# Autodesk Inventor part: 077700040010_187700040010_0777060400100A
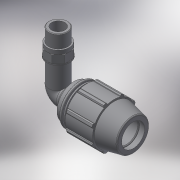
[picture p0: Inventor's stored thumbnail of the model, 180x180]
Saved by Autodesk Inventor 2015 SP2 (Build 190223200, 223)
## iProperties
Created: 2017-02
Part Number: 077700040010_187700040010_0777060400100A
Material: Generic
Description: PLASSON 90° ELBOW MALE WITH INTEGRAL BRASS THREAD 40-1"
Document SubType Name: Modeling
Designer: KIM
Mass: 174.249 g
Surface Area: 431.906 cm^2
Volume: 174.249 cm^3
Density: 1 g/cm^3
Appearance: Default
Author: KIM
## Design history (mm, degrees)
derived "07770.ipt"
feature "Solid1::07770.ipt"
tag "TaggingFeature1"
body "Solid1"
other parameters: "d4" = 10.33333, "d5" = 31, "d7" = 82, "d9" = 17.71429, "d11" = 4.13333, "d13" = 120 deg, "d14" = 56, "d15" = 12 deg, "d16" = 71.34, "d18" = 2, "d19" = 35 deg, "d20" = 17.5 deg, "d21" = 76.26, "d23" = 0, "d25" = 360 deg, "d27" = 1.64, "d33" = 0.8, "d42" = 45.88, "d43" = 2.46, "d46" = 1.2, "d51" = 124, "d68" = 8.26667, "d72" = 88, "d73" = 33.249, "d75" = 38.23635, "d76" = 23.2743, "d79" = 13.2996, "d80" = 0.99747, "d83" = 0, "d84" = 0, "d91" = 61.5, "d93" = 84, "d94" = 33.249, "d95" = 23.2743, "d96" = 8.26667, "d97" = 50 deg, "d98" = 2.06667, "d99" = 69.1998, "d100" = 2.06667, "d101" = 2.06667, "d105" = 2, "d106" = 39.8988, "d108" = 12, "d109" = 0, "E_" = 82, "A_" = 124, "l_" = 84, "A_1" = 88, "R_" = 33.249
